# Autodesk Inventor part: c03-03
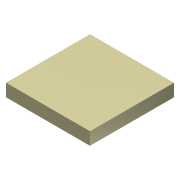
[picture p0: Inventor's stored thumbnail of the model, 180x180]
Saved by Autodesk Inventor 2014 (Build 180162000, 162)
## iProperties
Created: 2011-11
Part Number: c03-03
Material: Iron, Cast
Document SubType Name: Modeling
Designer: Thom Tremblay
Density: 7.25 g/cm^3
Mass: 1087.5 g
Surface Area: 260 cm^2
Volume: 150 cm^3
Appearance: Nylon 6
Author: Thom Tremblay
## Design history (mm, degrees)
sketch "Sketch1"
  geometry: L1 (50, -50)-(-50, -50); L2 (-50, -50)-(-50, 50); L3 (-50, 50)-(50, 50); L4 (50, 50)-(50, -50); 3 further points
  constraints: 8 end point, 2 midpoint, 2 parallel, 2 perpendicular, 1 horizontal, 1 horizontal alignment, 1 vertical alignment
  dimensions: "d0" = 100 distance of L2.end L3.end
extrude "Extrusion1" new body sketch "Sketch1" distance "d1" = 15; taper "d2" = 0 deg
body "Solid1"
